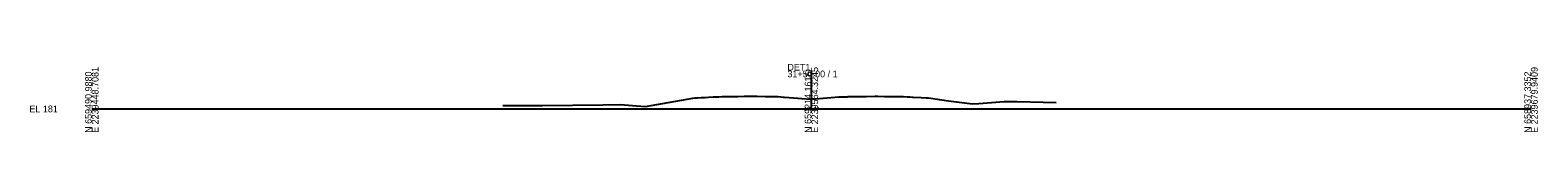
# Model space of a CAD drawing. Extents: x -26 to 1603, y -10 to 9524.
# Drawn here: x 974 to 1603, y 1990 to 2019 of the extents above; entities that cross this region are included whole.
import ezdxf

# ---------------------------------------------------------------- set-up
doc = ezdxf.new("R2010")
doc.units = 0
for name, color, linetype in [('Default', 7, 'Continuous'), ('Exist Cross Section Cell', 7, 'Continuous'), ('Exist XS Center Line Elevation Label', 7, 'Continuous'), ('Exist XS Ground Line', 7, 'Continuous')]:
    doc.layers.add(name, color=color, linetype=linetype)

msp = doc.modelspace()

# ---------------------------------------------------------------- linework, layer by layer
at = {"layer": 'Exist Cross Section Cell'}
for p, q in [((1300, 2000), (1300, 2015.99)), ((1000, 2000), (1300, 2000)), ((1300, 2000), (1600, 2000))]:
    msp.add_line(p, q, dxfattribs=at)
at = {"layer": 'Exist XS Ground Line'}
for p, q in [((1257.12, 2004.86), (1259.01, 2005.03)), ((1259.01, 2005.03), (1259.36, 2005.03)), ((1259.36, 2005.03), (1260.17, 2005.05)), ((1260.17, 2005.05), (1261.03, 2005.08)), ((1261.03, 2005.08), (1261.38, 2005.09)), ((1261.38, 2005.09), (1262.83, 2005.11)), ((1262.83, 2005.11), (1265.48, 2005.15)), ((1265.48, 2005.15), (1266.58, 2005.17)), ((1266.58, 2005.17), (1269.27, 2005.23)), ((1269.27, 2005.23), (1272, 2005.29)), ((1272, 2005.29), (1272.66, 2005.3)), ((1272.66, 2005.3), (1273.47, 2005.33)), ((1273.47, 2005.33), (1274.58, 2005.3)), ((1274.58, 2005.3), (1274.9, 2005.29)), ((1274.9, 2005.29), (1276.94, 2005.26)), ((1276.94, 2005.26), (1277.42, 2005.25)), ((1277.42, 2005.25), (1280.76, 2005.21)), ((1280.76, 2005.21), (1282.84, 2005.18)), ((1282.84, 2005.18), (1283.86, 2005.16)), ((1283.86, 2005.16), (1284.76, 2005.18)), ((1284.76, 2005.18), (1285.4, 2005.15)), ((1285.4, 2005.15), (1286.1, 2005.13)), ((1286.1, 2005.13), (1288.34, 2004.94)), ((1311.4, 2005), (1312.53, 2005.03)), ((1312.53, 2005.03), (1314.96, 2005.1)), ((1314.96, 2005.1), (1315.35, 2005.11)), ((1315.35, 2005.11), (1315.79, 2005.11)), ((1315.79, 2005.11), (1320.77, 2005.19)), ((1320.77, 2005.19), (1322.81, 2005.22)), ((1322.81, 2005.22), (1326.44, 2005.27)), ((1326.44, 2005.27), (1327.76, 2005.26)), ((1327.76, 2005.26), (1330.45, 2005.22)), ((1330.45, 2005.22), (1331.6, 2005.2)), ((1331.6, 2005.2), (1334.4, 2005.16)), ((1334.4, 2005.16), (1337.02, 2005.13)), ((1337.02, 2005.13), (1337.65, 2005.13)), ((1337.65, 2005.13), (1338.45, 2005.12)), ((1338.45, 2005.12), (1339.89, 2005.08)), ((1339.89, 2005.08), (1340.82, 2005.05)), ((1340.82, 2005.05), (1341.1, 2004.97)), ((1171.32, 2001.46), (1171.76, 2001.38)), ((1171.76, 2001.38), (1187.95, 2001.38)), ((1187.95, 2001.38), (1213.04, 2001.69)), ((1213.04, 2001.69), (1220.45, 2001.81)), ((1220.45, 2001.81), (1227.07, 2001.22)), ((1227.07, 2001.22), (1230.78, 2001.04)), ((1230.78, 2001.04), (1250.54, 2004.5)), ((1250.54, 2004.5), (1251.35, 2004.59)), ((1251.35, 2004.59), (1251.93, 2004.63)), ((1251.93, 2004.63), (1252.48, 2004.67)), ((1252.48, 2004.67), (1254.01, 2004.72)), ((1254.01, 2004.72), (1255.74, 2004.79)), ((1255.74, 2004.79), (1257.12, 2004.86)), ((1288.34, 2004.94), (1288.83, 2004.9)), ((1288.83, 2004.9), (1290.66, 2004.77)), ((1290.66, 2004.77), (1299.66, 2004.04)), ((1299.66, 2004.04), (1300, 2004.07)), ((1300, 2004.07), (1308.27, 2004.76)), ((1308.27, 2004.76), (1311.4, 2005)), ((1341.1, 2004.97), (1342.13, 2004.9)), ((1342.13, 2004.9), (1342.44, 2004.89)), ((1342.44, 2004.89), (1345.74, 2004.74)), ((1345.74, 2004.74), (1347.86, 2004.59)), ((1347.86, 2004.59), (1348.77, 2004.55)), ((1348.77, 2004.55), (1357.2, 2003.41)), ((1357.2, 2003.41), (1367.21, 2002.05)), ((1367.21, 2002.05), (1369.73, 2002.25)), ((1369.73, 2002.25), (1380.38, 2003.13)), ((1380.38, 2003.13), (1385.78, 2003.06)), ((1385.78, 2003.06), (1402.07, 2002.68))]:
    msp.add_line(p, q, dxfattribs=at)

# ---------------------------------------------------------------- texts
at = {"layer": 'Default'}
msp.add_text('-', height=0.0001, dxfattribs=at).set_placement((1000, 2000))
msp.add_text('-', height=0.0001, dxfattribs=at).set_placement((1000, 2000))
at = {"layer": 'Exist Cross Section Cell'}
for s, p in [('DET1', (1290, 2015.99)), ('31+50.00 / 1', (1290, 2013.19)), ('EL 181', (974, 1998.6))]:
    msp.add_text(s, height=2.8, dxfattribs=at).set_placement(p)
for s, p in [('N 659490.9880', (1000, 1990)), ('E 2239448.7081', (1002.8, 1990)), ('N 659214.1616', (1300, 1990)), ('E 2239564.3245', (1302.8, 1990)), ('N 658937.3352', (1600, 1990)), ('E 2239679.9409', (1602.8, 1990))]:
    msp.add_text(s, height=2.8, rotation=90, dxfattribs=at).set_placement(p)
at = {"layer": 'Exist XS Center Line Elevation Label'}
msp.add_text('185.07', height=1.5, dxfattribs=at).set_placement((1296.95, 1999.32))

doc.saveas('drawing.dxf')
